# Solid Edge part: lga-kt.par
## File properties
Author: nakano
Template: iso metric part.par
Last saved by: nakano
Revision: 8
Application: Solid Edge
Density: 1261.46340388235 kg/m^3
Accuracy: 0.990
Username: nakano
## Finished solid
Body 1: solid body, 7 faces, 14 edges, 8 vertices.
  Faces by surface: plane 6, cylinder 1
  Edges by curve: line 12, circle 2
Bounding box of the edges (mm): 64.000 x 3.000 x 26.000, from (-32.9075, 0, -0.0848) to (31.0925, 3, 25.9152).
Cylindrical faces by radius (mm): R5 x1
Planar faces by outward normal: +x 1, +y 1, +z 1, -x 1, -y 1, -z 1
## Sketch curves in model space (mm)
circle centre (-0.8455, 0, 13.39) radius 5
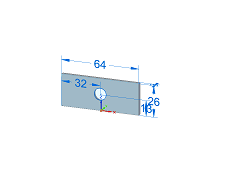
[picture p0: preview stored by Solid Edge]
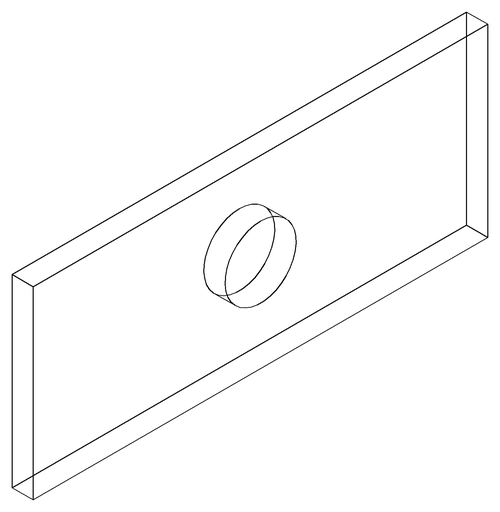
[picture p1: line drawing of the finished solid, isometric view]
